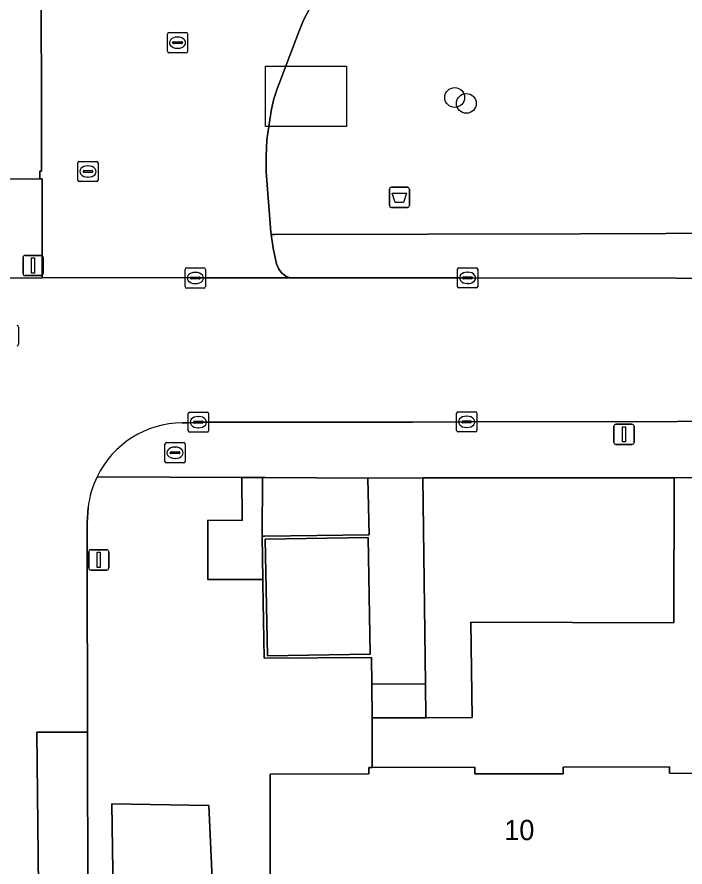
# Model space of a CAD drawing. Extents: x 161477 to 163040, y 383680 to 384871.
# Drawn here: x 162380.94 to 162413.91, y 384149.4 to 384191.39 of the extents above; entities that cross this region are included whole.
import ezdxf

# ---------------------------------------------------------------- set-up
doc = ezdxf.new("R2010")
doc.units = 0
for name, color, linetype in [('IMGEO_Afvalbak', 7, 'Continuous'), ('IMGEO_Boom', 7, 'Continuous'), ('IMGEO_Brandkraan', 7, 'Continuous'), ('IMGEO_Groenvoorziening', 7, 'Continuous'), ('IMGEO_Kolk', 7, 'Continuous'), ('IMGEO_Lichtmast', 7, 'Continuous'), ('IMGEO_Pand', 7, 'Continuous'), ('IMGEO_Pand_nummerreeks', 7, 'Continuous'), ('IMGEO_Pand_vergunning_verleend', 7, 'Continuous'), ('IMGEO_Parkeervlak_open', 7, 'Continuous'), ('IMGEO_Rijbaan_lokaal_open', 7, 'Continuous'), ('IMGEO_Rioolput', 7, 'Continuous'), ('IMGEO_Verkeersbordpaal', 7, 'Continuous'), ('IMGEO_Voetpad_open', 7, 'Continuous')]:
    doc.layers.add(name, color=color, linetype=linetype)

msp = doc.modelspace()

# ---------------------------------------------------------------- linework, layer by layer
at = {"layer": 'IMGEO_Afvalbak'}
for p, q in [((162399.318, 384182.077), (162399.318, 384182.877)), ((162399.318, 384182.877), (162399.318, 384182.077)), ((162399.418, 384182.977), (162400.208, 384182.977)), ((162400.208, 384182.977), (162399.418, 384182.977)), ((162400.308, 384182.877), (162400.308, 384182.077)), ((162400.308, 384182.077), (162400.308, 384182.877)), ((162400.208, 384181.977), (162399.418, 384181.977)), ((162399.418, 384181.977), (162400.208, 384181.977))]:
    msp.add_line(p, q, dxfattribs=at)
msp.add_lwpolyline([(162399.461, 384182.691), (162400.165, 384182.691), (162400.016, 384182.221), (162399.61, 384182.221), (162399.461, 384182.691)], dxfattribs=at)
for centre, start, end in [((162399.418, 384182.877), 90, 180), ((162399.418, 384182.877), 90, 180), ((162400.208, 384182.877), 0, 90), ((162400.208, 384182.877), 360, 90), ((162399.418, 384182.077), 180, 270), ((162399.418, 384182.077), 180, 270), ((162400.208, 384182.077), 270, 0), ((162400.208, 384182.077), 270, 0)]:
    msp.add_arc(centre, 0.1, start, end, dxfattribs=at)
at = {"layer": 'IMGEO_Boom'}
for centre in [(162402.543, 384187.41), (162403.118, 384187.12)]:
    msp.add_circle(centre, 0.489, dxfattribs=at)
at = {"layer": 'IMGEO_Brandkraan'}
for p, q in [((162388.239, 384169.434), (162388.239, 384170.286)), ((162388.314, 384170.36), (162389.166, 384170.36)), ((162388.727, 384170.14), (162388.752, 384170.14)), ((162389.24, 384170.286), (162389.24, 384169.434)), ((162388.498, 384169.854), (162388.498, 384169.866)), ((162388.936, 384169.817), (162388.538, 384169.817)), ((162388.541, 384169.903), (162388.939, 384169.903)), ((162388.982, 384169.866), (162388.982, 384169.854)), ((162389.166, 384169.36), (162388.314, 384169.36)), ((162388.75, 384169.58), (162388.725, 384169.58))]:
    msp.add_line(p, q, dxfattribs=at)
for points in [[(162388.239, 384169.434), (162388.239, 384170.286)], [(162388.314, 384170.36), (162389.166, 384170.36)], [(162389.24, 384170.286), (162389.24, 384169.434)], [(162389.166, 384169.36), (162388.314, 384169.36)]]:
    msp.add_lwpolyline(points, dxfattribs=at)
for centre, radius, start, end in [((162388.316, 384170.284), 0.0765, 91.552, 178.448), ((162388.316, 384170.284), 0.0765, 91.552, 178.448), ((162389.164, 384170.284), 0.0765, 1.552, 88.448), ((162389.164, 384170.284), 0.0765, 1.552, 88.448), ((162388.538, 384169.863), 0.0403, 85.8775, 175.7526), ((162388.535, 384169.853), 0.0366, 178.938, 274.7102), ((162388.939, 384169.86), 0.043, 264.8664, 352.4533), ((162388.943, 384169.865), 0.0386, 1.7309, 96.639), ((162388.316, 384169.436), 0.0765, 181.552, 268.448), ((162388.316, 384169.436), 0.0765, 181.552, 268.448), ((162389.164, 384169.436), 0.0765, 271.552, 358.448), ((162389.164, 384169.436), 0.0765, 271.552, 358.448)]:
    msp.add_arc(centre, radius, start, end, dxfattribs=at)
for centre, major_axis, ratio, start_param, end_param in [((162388.726, 384169.86), (-0.387, 0.002), 0.722429, 4.712389, 7.853982), ((162388.751, 384169.86), (-0.39, 0.002), 0.717154, 1.570796, 4.712389)]:
    msp.add_ellipse(centre, major_axis=major_axis, ratio=ratio, start_param=start_param, end_param=end_param, dxfattribs=at)
at = {"layer": 'IMGEO_Groenvoorziening'}
for points in [[(162395.374, 384191.796), (162395.078, 384191.238), (162394.841, 384190.652), (162393.784, 384187.84), (162393.619, 384187.339), (162393.494, 384186.827), (162393.41, 384186.306), (162393.266, 384185.323), (162393.231, 384184.535), (162393.231, 384183.746), (162393.465, 384180.756), (162393.481, 384180.644), (162393.647, 384180.645), (162408.76, 384180.682), (162425.605, 384180.743), (162425.718, 384197.318)], [(162393.431, 384153.979), (162398.31, 384153.993), (162398.309, 384154.313), (162398.47, 384154.313), (162398.463, 384156.769), (162398.45, 384158.429), (162398.444, 384159.741), (162393.13, 384159.707), (162393.074, 384163.402), (162393.071, 384163.594), (162390.35, 384163.602), (162390.35, 384166.539), (162392.045, 384166.517), (162392.041, 384168.641), (162384.89, 384168.677)], [(162384.445, 384167.157), (162384.403, 384166.394), (162384.398, 384164.831), (162384.414, 384156.056), (162384.43, 384147.685), (162384.451, 384143.354), (162384.457, 384137.718), (162384.461, 384133.501), (162384.469, 384132.803), (162385.801, 384132.825), (162385.747, 384134.815), (162385.887, 384134.817), (162385.626, 384152.513), (162390.407, 384152.435), (162390.839, 384143.031), (162391.599, 384139.791), (162393.903, 384138.082), (162397.075, 384140.334), (162398.073, 384146.158), (162393.433, 384146.157), (162393.431, 384153.979)], [(162450.344, 384152.729), (162450.329, 384154.952), (162430.2, 384167.193), (162423.686, 384161.363), (162423.619, 384153.869), (162418.419, 384153.886), (162417.087, 384153.89), (162416.837, 384153.891), (162416.843, 384152.651), (162416.87, 384146.287), (162415.691, 384137.403), (162394.498, 384137.641), (162393.903, 384138.082), (162391.599, 384139.791), (162390.839, 384143.031), (162390.407, 384152.435), (162385.626, 384152.513), (162385.887, 384134.817), (162391.505, 384134.881), (162391.505, 384127.045), (162385.81, 384127.045), (162385.81, 384128.801), (162384.6, 384128.793), (162384.527, 384127.843)]]:
    msp.add_lwpolyline(points, dxfattribs=at)
msp.add_lwpolyline([(162401.097, 384158.446), (162401.12, 384156.771), (162403.406, 384156.777), (162403.34, 384161.501), (162413.359, 384161.455), (162413.383, 384168.63), (162400.977, 384168.63)], close=True, dxfattribs=at)
msp.add_arc((162389.111, 384166.616), 4.697, 153.9752, 173.3886, dxfattribs=at)
at = {"layer": 'IMGEO_Kolk'}
for p, q in [((162388.435, 384190.619), (162389.287, 384190.619)), ((162388.36, 384189.693), (162388.36, 384190.545)), ((162388.848, 384190.399), (162388.873, 384190.399)), ((162389.361, 384190.545), (162389.361, 384189.693)), ((162388.619, 384190.113), (162388.619, 384190.125)), ((162389.057, 384190.076), (162388.659, 384190.076)), ((162388.662, 384190.162), (162389.06, 384190.162)), ((162388.871, 384189.839), (162388.846, 384189.839)), ((162389.103, 384190.125), (162389.103, 384190.113)), ((162389.287, 384189.619), (162388.435, 384189.619)), ((162389.239, 384178.068), (162389.239, 384178.92)), ((162389.314, 384178.994), (162390.166, 384178.994)), ((162390.24, 384178.92), (162390.24, 384178.068)), ((162402.676, 384178.075), (162402.676, 384178.927)), ((162402.751, 384179.001), (162403.603, 384179.001)), ((162403.677, 384178.927), (162403.677, 384178.075)), ((162389.498, 384178.488), (162389.498, 384178.5)), ((162389.936, 384178.451), (162389.538, 384178.451)), ((162389.541, 384178.537), (162389.939, 384178.537)), ((162389.727, 384178.774), (162389.752, 384178.774)), ((162389.982, 384178.5), (162389.982, 384178.488)), ((162402.935, 384178.495), (162402.935, 384178.507)), ((162403.373, 384178.458), (162402.975, 384178.458)), ((162402.978, 384178.544), (162403.376, 384178.544)), ((162403.164, 384178.781), (162403.189, 384178.781)), ((162403.419, 384178.507), (162403.419, 384178.495)), ((162390.166, 384177.994), (162389.314, 384177.994)), ((162389.75, 384178.214), (162389.725, 384178.214)), ((162403.603, 384178.001), (162402.751, 384178.001)), ((162403.187, 384178.221), (162403.162, 384178.221)), ((162389.389, 384170.946), (162389.389, 384171.798)), ((162389.464, 384171.872), (162390.316, 384171.872)), ((162390.39, 384171.798), (162390.39, 384170.946)), ((162402.634, 384170.962), (162402.634, 384171.814)), ((162402.709, 384171.888), (162403.561, 384171.888)), ((162403.635, 384171.814), (162403.635, 384170.962)), ((162389.648, 384171.366), (162389.648, 384171.378)), ((162390.086, 384171.329), (162389.688, 384171.329)), ((162389.691, 384171.415), (162390.089, 384171.415)), ((162389.877, 384171.652), (162389.902, 384171.652)), ((162390.132, 384171.378), (162390.132, 384171.366)), ((162402.893, 384171.382), (162402.893, 384171.394)), ((162403.331, 384171.345), (162402.933, 384171.345)), ((162402.936, 384171.431), (162403.334, 384171.431)), ((162403.122, 384171.668), (162403.147, 384171.668)), ((162403.377, 384171.394), (162403.377, 384171.382)), ((162390.316, 384170.872), (162389.464, 384170.872)), ((162389.9, 384171.092), (162389.875, 384171.092)), ((162403.561, 384170.888), (162402.709, 384170.888)), ((162403.145, 384171.108), (162403.12, 384171.108))]:
    msp.add_line(p, q, dxfattribs=at)
for points in [[(162388.435, 384190.619), (162389.287, 384190.619)], [(162388.36, 384189.693), (162388.36, 384190.545)], [(162389.361, 384190.545), (162389.361, 384189.693)], [(162389.287, 384189.619), (162388.435, 384189.619)], [(162389.239, 384178.068), (162389.239, 384178.92)], [(162389.314, 384178.994), (162390.166, 384178.994)], [(162390.24, 384178.92), (162390.24, 384178.068)], [(162402.676, 384178.075), (162402.676, 384178.927)], [(162402.751, 384179.001), (162403.603, 384179.001)], [(162403.677, 384178.927), (162403.677, 384178.075)], [(162390.166, 384177.994), (162389.314, 384177.994)], [(162403.603, 384178.001), (162402.751, 384178.001)], [(162389.389, 384170.946), (162389.389, 384171.798)], [(162389.464, 384171.872), (162390.316, 384171.872)], [(162390.39, 384171.798), (162390.39, 384170.946)], [(162402.634, 384170.962), (162402.634, 384171.814)], [(162402.709, 384171.888), (162403.561, 384171.888)], [(162403.635, 384171.814), (162403.635, 384170.962)], [(162390.316, 384170.872), (162389.464, 384170.872)], [(162403.561, 384170.888), (162402.709, 384170.888)]]:
    msp.add_lwpolyline(points, dxfattribs=at)
for centre, radius, start, end in [((162388.437, 384190.543), 0.0765, 91.552, 178.448), ((162388.437, 384190.543), 0.0765, 91.552, 178.448), ((162389.285, 384190.543), 0.0765, 1.552, 88.448), ((162389.285, 384190.543), 0.0765, 1.552, 88.448), ((162388.659, 384190.122), 0.0403, 85.8775, 175.7526), ((162388.656, 384190.112), 0.0366, 178.938, 274.7102), ((162389.06, 384190.119), 0.043, 264.8664, 352.4533), ((162389.064, 384190.124), 0.0386, 1.7309, 96.639), ((162388.437, 384189.695), 0.0765, 181.552, 268.448), ((162388.437, 384189.695), 0.0765, 181.552, 268.448), ((162389.285, 384189.695), 0.0765, 271.552, 358.448), ((162389.285, 384189.695), 0.0765, 271.552, 358.448), ((162389.316, 384178.918), 0.0765, 91.552, 178.448), ((162389.316, 384178.918), 0.0765, 91.552, 178.448), ((162390.164, 384178.918), 0.0765, 1.552, 88.448), ((162390.164, 384178.918), 0.0765, 1.552, 88.448), ((162402.753, 384178.925), 0.0765, 91.552, 178.448), ((162402.753, 384178.925), 0.0765, 91.552, 178.448), ((162403.601, 384178.925), 0.0765, 1.552, 88.448), ((162403.601, 384178.925), 0.0765, 1.552, 88.448), ((162389.538, 384178.497), 0.0403, 85.8775, 175.7526), ((162389.535, 384178.487), 0.0366, 178.938, 274.7102), ((162389.939, 384178.494), 0.043, 264.8664, 352.4533), ((162389.943, 384178.499), 0.0386, 1.7309, 96.639), ((162402.975, 384178.504), 0.0403, 85.8775, 175.7526), ((162402.972, 384178.494), 0.0366, 178.938, 274.7102), ((162403.376, 384178.501), 0.043, 264.8664, 352.4533), ((162403.38, 384178.506), 0.0386, 1.7309, 96.639), ((162389.316, 384178.07), 0.0765, 181.552, 268.448), ((162389.316, 384178.07), 0.0765, 181.552, 268.448), ((162390.164, 384178.07), 0.0765, 271.552, 358.448), ((162390.164, 384178.07), 0.0765, 271.552, 358.448), ((162402.753, 384178.077), 0.0765, 181.552, 268.448), ((162402.753, 384178.077), 0.0765, 181.552, 268.448), ((162403.601, 384178.077), 0.0765, 271.552, 358.448), ((162403.601, 384178.077), 0.0765, 271.552, 358.448), ((162389.466, 384171.796), 0.0765, 91.552, 178.448), ((162389.466, 384171.796), 0.0765, 91.552, 178.448), ((162390.314, 384171.796), 0.0765, 1.552, 88.448), ((162390.314, 384171.796), 0.0765, 1.552, 88.448), ((162402.711, 384171.812), 0.0765, 91.552, 178.448), ((162402.711, 384171.812), 0.0765, 91.552, 178.448), ((162403.559, 384171.812), 0.0765, 1.552, 88.448), ((162403.559, 384171.812), 0.0765, 1.552, 88.448), ((162389.688, 384171.375), 0.0403, 85.8775, 175.7526), ((162389.685, 384171.365), 0.0366, 178.938, 274.7102), ((162390.089, 384171.372), 0.043, 264.8664, 352.4533), ((162390.093, 384171.377), 0.0386, 1.7309, 96.639), ((162402.933, 384171.391), 0.0403, 85.8775, 175.7526), ((162402.93, 384171.381), 0.0366, 178.938, 274.7102), ((162403.334, 384171.388), 0.043, 264.8664, 352.4533), ((162403.338, 384171.393), 0.0386, 1.7309, 96.639), ((162389.466, 384170.948), 0.0765, 181.552, 268.448), ((162389.466, 384170.948), 0.0765, 181.552, 268.448), ((162390.314, 384170.948), 0.0765, 271.552, 358.448), ((162390.314, 384170.948), 0.0765, 271.552, 358.448), ((162402.711, 384170.964), 0.0765, 181.552, 268.448), ((162402.711, 384170.964), 0.0765, 181.552, 268.448), ((162403.559, 384170.964), 0.0765, 271.552, 358.448), ((162403.559, 384170.964), 0.0765, 271.552, 358.448)]:
    msp.add_arc(centre, radius, start, end, dxfattribs=at)
for centre, major_axis, ratio, start_param, end_param in [((162388.847, 384190.119), (-0.387, 0.002), 0.722429, 4.712389, 7.853982), ((162388.872, 384190.119), (-0.39, 0.002), 0.717154, 1.570796, 4.712389), ((162389.726, 384178.494), (-0.387, 0.002), 0.722429, 4.712389, 7.853982), ((162389.751, 384178.494), (-0.39, 0.002), 0.717154, 1.570796, 4.712389), ((162403.163, 384178.501), (-0.387, 0.002), 0.722429, 4.712389, 7.853982), ((162403.188, 384178.501), (-0.39, 0.002), 0.717154, 1.570796, 4.712389), ((162389.876, 384171.372), (-0.387, 0.002), 0.722429, 4.712389, 7.853982), ((162389.901, 384171.372), (-0.39, 0.002), 0.717154, 1.570796, 4.712389), ((162403.121, 384171.388), (-0.387, 0.002), 0.722429, 4.712389, 7.853982), ((162403.146, 384171.388), (-0.39, 0.002), 0.717154, 1.570796, 4.712389)]:
    msp.add_ellipse(centre, major_axis=major_axis, ratio=ratio, start_param=start_param, end_param=end_param, dxfattribs=at)
at = {"layer": 'IMGEO_Lichtmast'}
for p, q in [((162410.405, 384170.37), (162410.405, 384171.17)), ((162410.405, 384171.17), (162410.405, 384170.37)), ((162410.505, 384171.27), (162411.295, 384171.27)), ((162411.295, 384171.27), (162410.505, 384171.27)), ((162411.395, 384171.17), (162411.395, 384170.37)), ((162411.395, 384170.37), (162411.395, 384171.17)), ((162411.295, 384170.27), (162410.505, 384170.27)), ((162410.505, 384170.27), (162411.295, 384170.27)), ((162384.575, 384165.069), (162385.365, 384165.069)), ((162385.365, 384165.069), (162384.575, 384165.069)), ((162384.475, 384164.169), (162384.475, 384164.969)), ((162384.475, 384164.969), (162384.475, 384164.169)), ((162385.465, 384164.969), (162385.465, 384164.169)), ((162385.465, 384164.169), (162385.465, 384164.969)), ((162385.365, 384164.069), (162384.575, 384164.069)), ((162384.575, 384164.069), (162385.365, 384164.069))]:
    msp.add_line(p, q, dxfattribs=at)
for points in [[(162410.825, 384171.145), (162410.975, 384171.145), (162410.975, 384170.395), (162410.825, 384170.395), (162410.825, 384171.145)], [(162384.895, 384164.944), (162385.045, 384164.944), (162385.045, 384164.194), (162384.895, 384164.194), (162384.895, 384164.944)]]:
    msp.add_lwpolyline(points, dxfattribs=at)
for centre, start, end in [((162410.505, 384171.17), 90, 180), ((162410.505, 384171.17), 90, 180), ((162411.295, 384171.17), 0, 90), ((162411.295, 384171.17), 360, 90), ((162410.505, 384170.37), 180, 270), ((162410.505, 384170.37), 180, 270), ((162411.295, 384170.37), 270, 0), ((162411.295, 384170.37), 270, 0), ((162384.575, 384164.969), 90, 180), ((162384.575, 384164.969), 90, 180), ((162385.365, 384164.969), 0, 90), ((162385.365, 384164.969), 360, 90), ((162384.575, 384164.169), 180, 270), ((162384.575, 384164.169), 180, 270), ((162385.365, 384164.169), 270, 0), ((162385.365, 384164.169), 270, 0)]:
    msp.add_arc(centre, 0.1, start, end, dxfattribs=at)
at = {"layer": 'IMGEO_Pand'}
msp.add_lwpolyline([(162349.595, 384212.314), (162349.59, 384183.191), (162373.395, 384183.196), (162373.395, 384183.376), (162382.059, 384183.395), (162382.058, 384183.765), (162382.138, 384183.765), (162382.135, 384195.395)], dxfattribs=at)
for points in [[(162393.304, 384159.832), (162398.375, 384159.908), (162398.265, 384165.669), (162393.194, 384165.593)], [(162416.843, 384152.651), (162416.837, 384153.891), (162416.837, 384154.001), (162413.142, 384154.028), (162413.141, 384154.348), (162407.9, 384154.328), (162407.901, 384154.008), (162403.537, 384154.004), (162403.536, 384154.324), (162398.47, 384154.313), (162398.309, 384154.313), (162398.31, 384153.993), (162393.431, 384153.979), (162393.433, 384146.157), (162398.073, 384146.158), (162397.075, 384140.334), (162397.045, 384140.16), (162414.456, 384140.188), (162413.41, 384146.272), (162416.87, 384146.287)]]:
    msp.add_lwpolyline(points, close=True, dxfattribs=at)
at = {"layer": 'IMGEO_Pand_vergunning_verleend'}
msp.add_lwpolyline([(162393.197, 384185.985), (162393.197, 384188.965), (162397.197, 384188.965), (162397.197, 384185.985)], close=True, dxfattribs=at)
at = {"layer": 'IMGEO_Parkeervlak_open'}
msp.add_lwpolyline([(162384.43, 384147.685), (162384.414, 384156.056), (162381.922, 384156.051), (162382.117, 384137.738), (162384.457, 384137.718), (162384.451, 384143.354)], close=True, dxfattribs=at)
at = {"layer": 'IMGEO_Rijbaan_lokaal_open'}
for points in [[(162382.135, 384195.395), (162382.138, 384183.765), (162382.058, 384183.765), (162382.059, 384183.395), (162382.18, 384183.394), (162382.179, 384178.509), (162383.802, 384178.52), (162389.74, 384178.495), (162394.404, 384178.497), (162394.202, 384178.581), (162393.995, 384178.743), (162393.839, 384178.956), (162393.746, 384179.202), (162393.576, 384179.974), (162393.481, 384180.644), (162393.465, 384180.756), (162393.231, 384183.746), (162393.231, 384184.535), (162393.266, 384185.323), (162393.41, 384186.306), (162393.494, 384186.827), (162393.619, 384187.339), (162393.784, 384187.84), (162394.841, 384190.652), (162395.078, 384191.238), (162395.374, 384191.796)], [(162420.98, 384178.465), (162413.481, 384178.492), (162403.177, 384178.502), (162394.404, 384178.497), (162389.74, 384178.495), (162383.802, 384178.52), (162382.179, 384178.509), (162373.047, 384178.488), (162370.356, 384178.487), (162354.103, 384178.434), (162351.438, 384178.435), (162335.829, 384178.406)], [(162389.098, 384171.347), (162389.404, 384171.346), (162389.89, 384171.373), (162398.224, 384171.366), (162400.467, 384171.373), (162403.135, 384171.389), (162413.531, 384171.412), (162418.228, 384171.418), (162420.603, 384171.425)], [(162384.527, 384127.843), (162384.6, 384128.793), (162384.628, 384129.15), (162384.508, 384129.159), (162384.469, 384132.803), (162384.461, 384133.501), (162384.457, 384137.718), (162382.117, 384137.738), (162381.922, 384156.051), (162384.414, 384156.056), (162384.398, 384164.831), (162384.403, 384166.394), (162384.445, 384167.157)]]:
    msp.add_lwpolyline(points, dxfattribs=at)
for centre, radius, start, end in [((162389.155, 384166.606), 4.741, 90.6899, 154.1008), ((162389.111, 384166.616), 4.697, 153.9752, 173.3886)]:
    msp.add_arc(centre, radius, start, end, dxfattribs=at)
at = {"layer": 'IMGEO_Rioolput'}
for p, q in [((162383.938, 384183.33), (162383.938, 384184.182)), ((162384.013, 384184.256), (162384.865, 384184.256)), ((162384.426, 384184.036), (162384.451, 384184.036)), ((162384.939, 384184.182), (162384.939, 384183.33)), ((162384.197, 384183.75), (162384.197, 384183.762)), ((162384.635, 384183.713), (162384.237, 384183.713)), ((162384.24, 384183.799), (162384.638, 384183.799)), ((162384.449, 384183.476), (162384.424, 384183.476)), ((162384.681, 384183.762), (162384.681, 384183.75)), ((162384.865, 384183.256), (162384.013, 384183.256)), ((162381.011, 384176.071), (162381.011, 384175.219))]:
    msp.add_line(p, q, dxfattribs=at)
for points in [[(162383.938, 384183.33), (162383.938, 384184.182)], [(162384.013, 384184.256), (162384.865, 384184.256)], [(162384.939, 384184.182), (162384.939, 384183.33)], [(162384.865, 384183.256), (162384.013, 384183.256)], [(162381.011, 384176.071), (162381.011, 384175.219)]]:
    msp.add_lwpolyline(points, dxfattribs=at)
for centre, radius, start, end in [((162384.015, 384184.18), 0.0765, 91.552, 178.448), ((162384.015, 384184.18), 0.0765, 91.552, 178.448), ((162384.863, 384184.18), 0.0765, 1.552, 88.448), ((162384.863, 384184.18), 0.0765, 1.552, 88.448), ((162384.237, 384183.759), 0.0403, 85.8775, 175.7526), ((162384.234, 384183.749), 0.0366, 178.938, 274.7102), ((162384.638, 384183.756), 0.043, 264.8664, 352.4533), ((162384.642, 384183.761), 0.0386, 1.7309, 96.639), ((162384.015, 384183.332), 0.0765, 181.552, 268.448), ((162384.015, 384183.332), 0.0765, 181.552, 268.448), ((162384.863, 384183.332), 0.0765, 271.552, 358.448), ((162384.863, 384183.332), 0.0765, 271.552, 358.448), ((162380.935, 384176.069), 0.0765, 1.552, 88.448), ((162380.935, 384176.069), 0.0765, 1.552, 88.448), ((162380.935, 384175.221), 0.0765, 271.552, 358.448), ((162380.935, 384175.221), 0.0765, 271.552, 358.448)]:
    msp.add_arc(centre, radius, start, end, dxfattribs=at)
for centre, major_axis, ratio, start_param, end_param in [((162384.425, 384183.756), (-0.387, 0.002), 0.722429, 4.712389, 7.853982), ((162384.45, 384183.756), (-0.39, 0.002), 0.717154, 1.570796, 4.712389)]:
    msp.add_ellipse(centre, major_axis=major_axis, ratio=ratio, start_param=start_param, end_param=end_param, dxfattribs=at)
at = {"layer": 'IMGEO_Verkeersbordpaal'}
for p, q in [((162381.235, 384178.71), (162381.235, 384179.51)), ((162381.235, 384179.51), (162381.235, 384178.71)), ((162381.335, 384179.61), (162382.125, 384179.61)), ((162382.125, 384179.61), (162381.335, 384179.61)), ((162382.225, 384179.51), (162382.225, 384178.71)), ((162382.225, 384178.71), (162382.225, 384179.51)), ((162382.125, 384178.61), (162381.335, 384178.61)), ((162381.335, 384178.61), (162382.125, 384178.61))]:
    msp.add_line(p, q, dxfattribs=at)
msp.add_lwpolyline([(162381.655, 384179.485), (162381.805, 384179.485), (162381.805, 384178.735), (162381.655, 384178.735), (162381.655, 384179.485)], dxfattribs=at)
for centre, start, end in [((162381.335, 384179.51), 90, 180), ((162381.335, 384179.51), 90, 180), ((162382.125, 384179.51), 0, 90), ((162382.125, 384179.51), 360, 90), ((162381.335, 384178.71), 180, 270), ((162381.335, 384178.71), 180, 270), ((162382.125, 384178.71), 270, 0), ((162382.125, 384178.71), 270, 0)]:
    msp.add_arc(centre, 0.1, start, end, dxfattribs=at)
at = {"layer": 'IMGEO_Voetpad_open'}
for points in [[(162351.438, 384178.435), (162354.103, 384178.434), (162370.356, 384178.487), (162373.047, 384178.488), (162382.179, 384178.509), (162382.18, 384183.394), (162382.059, 384183.395), (162373.395, 384183.376), (162373.395, 384183.196), (162349.59, 384183.191), (162349.595, 384212.314)], [(162425.718, 384197.318), (162425.605, 384180.743), (162408.76, 384180.682), (162393.647, 384180.645), (162393.481, 384180.644), (162393.576, 384179.974), (162393.746, 384179.202), (162393.839, 384178.956), (162393.995, 384178.743), (162394.202, 384178.581), (162394.404, 384178.497), (162403.177, 384178.502), (162413.481, 384178.492), (162420.98, 384178.465)], [(162384.89, 384168.677), (162392.041, 384168.641), (162393.053, 384168.636), (162393.189, 384168.635), (162398.262, 384168.611), (162400.977, 384168.63), (162413.383, 384168.63), (162417.548, 384168.644), (162427.405, 384168.602), (162427.613, 384168.697), (162433.962, 384172.795)], [(162420.603, 384171.425), (162418.228, 384171.418), (162413.531, 384171.412), (162403.135, 384171.389), (162400.467, 384171.373), (162398.224, 384171.366), (162389.89, 384171.373), (162389.404, 384171.346), (162389.098, 384171.347)]]:
    msp.add_lwpolyline(points, dxfattribs=at)
for points in [[(162393.053, 384168.636), (162392.041, 384168.641), (162392.045, 384166.517), (162390.35, 384166.539), (162390.35, 384163.602), (162393.071, 384163.594), (162393.039, 384165.738)], [(162398.262, 384168.611), (162393.189, 384168.635), (162393.053, 384168.636), (162393.039, 384165.738), (162393.151, 384165.739), (162398.326, 384165.8)], [(162400.977, 384168.63), (162398.262, 384168.611), (162398.326, 384165.8), (162393.151, 384165.739), (162393.039, 384165.738), (162393.071, 384163.594), (162393.074, 384163.402), (162393.13, 384159.707), (162398.444, 384159.741), (162398.45, 384158.429), (162401.097, 384158.446)], [(162418.525, 384162.295), (162417.538, 384162.29), (162417.548, 384168.644), (162413.383, 384168.63), (162413.359, 384161.455), (162403.34, 384161.501), (162403.406, 384156.777), (162401.12, 384156.771), (162398.463, 384156.769), (162398.47, 384154.313), (162403.536, 384154.324), (162403.537, 384154.004), (162407.901, 384154.008), (162407.9, 384154.328), (162413.141, 384154.348), (162413.142, 384154.028), (162416.837, 384154.001), (162416.837, 384153.891), (162417.087, 384153.89), (162418.419, 384153.886)], [(162398.265, 384165.669), (162398.375, 384159.908), (162393.304, 384159.832), (162393.194, 384165.593)], [(162401.12, 384156.771), (162401.097, 384158.446), (162398.45, 384158.429), (162398.463, 384156.769)]]:
    msp.add_lwpolyline(points, close=True, dxfattribs=at)
msp.add_arc((162389.155, 384166.606), 4.741, 90.6899, 154.1008, dxfattribs=at)

# ---------------------------------------------------------------- texts
at = {"layer": 'IMGEO_Pand_nummerreeks'}
msp.add_text('10', height=1, rotation=0.0516, dxfattribs=at).set_placement((162404.99, 384150.725))

doc.saveas('drawing.dxf')
